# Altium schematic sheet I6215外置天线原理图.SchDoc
size A4
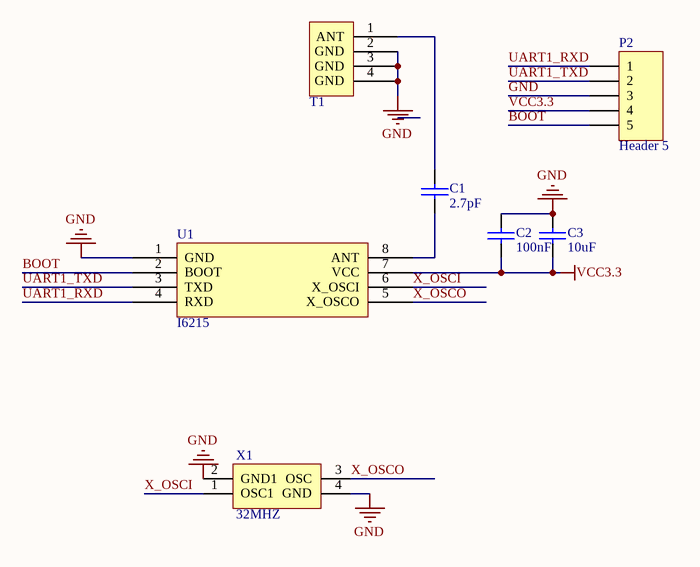
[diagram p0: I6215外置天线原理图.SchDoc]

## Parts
C1  2.7pF  [0402_C]
C2  100nF  [0402_C]
C3  10uF  [0402_C]
P2  Header 5  [HDR1X5]
T1  ANT  [IPEX]  (value not drawn)
U1  I6215  [SOP8]
X1  32MHZ  [crystal oscillator 24MHZ]

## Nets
GND: C2.1 C3.1 P2.3 T1.2(GND) T1.3(GND) T1.4(GND) U1.1(GND) X1.2(GND1) X1.4(GND)
VCC3.3: C2.2 C3.2 P2.4 U1.7(VCC)
BOOT: P2.5 U1.2(BOOT)
UART1_RXD: P2.1 U1.4(RXD)
UART1_TXD: P2.2 U1.3(TXD)
X_OSCI: U1.6(X_OSCI) X1.1(OSC1)
X_OSCO: U1.5(X_OSCO) X1.3(OSC)
NetC1_1: C1.1 T1.1(ANT)
NetC1_2: C1.2 U1.8(ANT)

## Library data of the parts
C1 = CAP: Capacitor
C2 C3 = CAP: Capacitor; Value: 1.2pF
P2 = Header 5: Header, 5-Pin
T1 = ANT_1
X1 = 16MHZ: value: 12MHZ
